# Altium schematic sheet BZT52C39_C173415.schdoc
size 127 x 101 mm
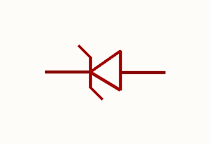
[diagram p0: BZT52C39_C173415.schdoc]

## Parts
D?  bzt52c39_c173415  [SOD-123_L2.7-W1.6-LS3.7-RD]  (value not drawn)

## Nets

Not connected (* = marked no-connect by the designer): D? 1(C) 2(A)

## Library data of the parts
D? = bzt52c39_c173415: 二极管配置:1个独立式;稳压值(标称值):39V;稳压值(范围):37V~41V;耗散功率(Pd):500mW;; Manufacturer: MDD(辰达半导体); AddInBom: yes; ModelId: ad7e39f9e5534b3c96ffdc5532ebb493; ModelName: SOD-123_L2.7-W1.6-H1.4-LS3.7; ModelTransform: 146.026,62.992,0,180,0,0,0.0005,0,0; Diode Configuration: 1个独立式; Zener Voltage(Nom): 39V; Reverse Leakage Current (Ir): 2uA@30V; Pd - Power Dissipation: 500mW; Impedance(Zzt): 100Ω; Tolerance: ±5%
